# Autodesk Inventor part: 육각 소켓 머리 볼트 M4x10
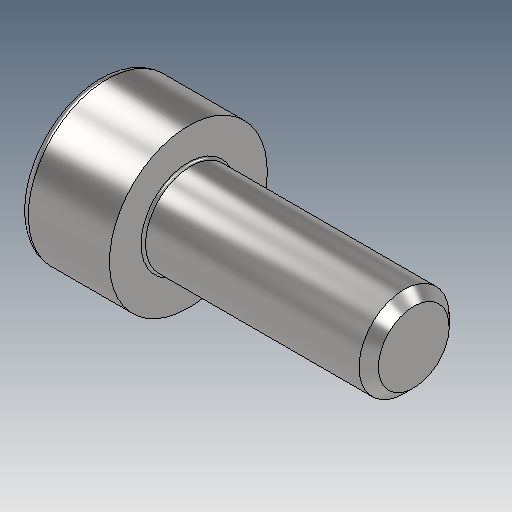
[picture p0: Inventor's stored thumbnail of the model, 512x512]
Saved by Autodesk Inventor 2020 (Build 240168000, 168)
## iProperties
Created: 2024-11
Part Number: 육각 소켓 머리 볼트 M4x10
Material: 강철, 연강
Description: 6각머리 태핑 나사
Document SubType Name: Modeling
Designer: shin
Density: 7.85 g/cm^3
Appearance: 기본값
Author: jhkim
Sending System: Autodesk Inventor 2025
Preprocessor: ST-DEVELOPER v20
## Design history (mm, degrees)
feature "Solid1"
node "솔리드1"
